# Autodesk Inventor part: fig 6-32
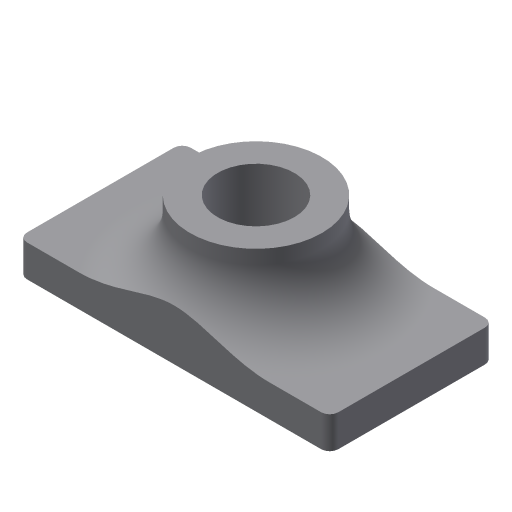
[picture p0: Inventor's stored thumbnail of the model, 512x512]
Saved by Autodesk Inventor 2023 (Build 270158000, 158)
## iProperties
Created: 2004-05
Part Number: fig 6-32
Document SubType Name: Modeling
Designer: CADCIM Technologies
Manufacturer: Standard
Standards Organization: Custom
Density: 1 g/cm^3
Material: Generic
Appearance: Default
Author: CADCIM Technologies
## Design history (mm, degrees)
sketch "Sketch1"
  geometry: L1 (-39.276, -18.692)-(33.721, -18.692); L2 (33.721, -18.692)-(33.721, 19.728); L3 (33.721, 19.728)-(-39.276, 19.728); L4 (-39.276, 19.728)-(-39.276, -18.692)
  constraints: 8 end point, 2 parallel, 1 horizontal, 1 perpendicular
extrude "Extrusion1" new body sketch "Sketch1" distance "d0" = 7.5; taper "d1" = 0 deg
fillet "Fillet1" dims "d2" = 2
sketch "Sketch2"
  geometry: C1 r 15.456 at (-2.778, 0.518)
  constraints: 1 centre point
extrude "Extrusion2" join sketch "Sketch2" distance "d3" = 17.25; taper "d4" = 0 deg
hole "Hole1" diameter "d8" = 18; stored, may be unused: countersink angle "d12" = 90 deg, drill point angle "d14" = 118 deg; dims "d6" = 10, "d7" = 10, "d9" = 6, "d10" = 4, "d11" = 2, "d13" = 8
fillet "Fillet2" dims "d5" = 14
body "Solid1"
